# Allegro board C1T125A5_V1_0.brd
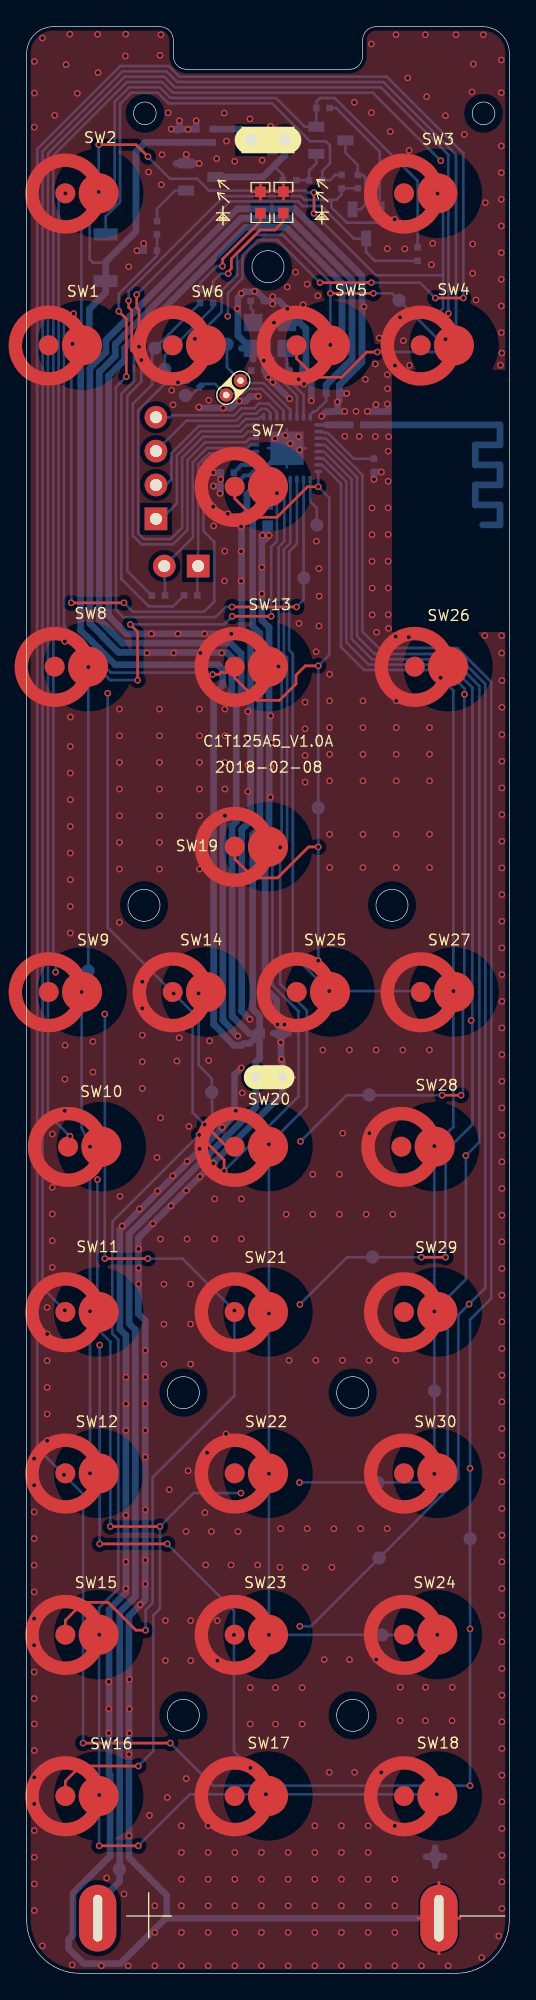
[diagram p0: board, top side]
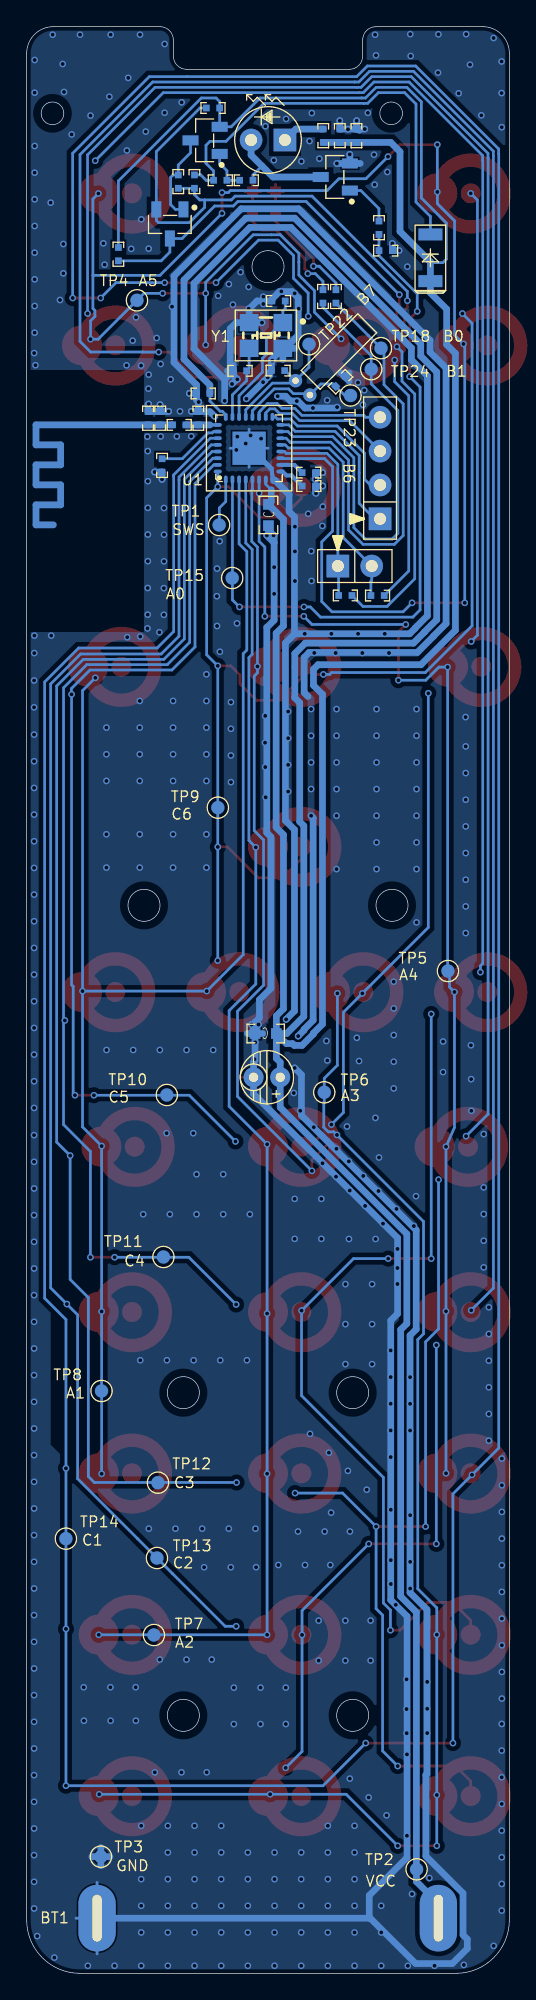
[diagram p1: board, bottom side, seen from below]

Outline 36.2 x 146 mm; copper layers: TOP, BOTTOM. Coordinates in mm from the lower left corner of the outline.
Outline path: circle c8.8,80.1 r1.2 ; circle c8.86,139.5 r0.85 ; circle c11.75,43.55 r1.2 ; circle c11.75,19.35 r1.2 ; circle c18.1,128 r1.2 ; circle c24.45,43.55 r1.2 ; circle c24.45,19.35 r1.2 ; circle c27.4,80.1 r1.2 ; circle c34.26,139.5 r0.85 ; 0,144 0,4 arc(1.17,1.17) 4,0 32.2,0 arc(35.03,1.17) 36.2,4 36.2,144 arc(35.61,145.41) 34.2,146 26.2,146 arc(25.49,145.71) 25.2,145 25.2,143.8 arc(24.91,143.09) 24.2,142.8 12,142.8 arc(11.29,143.09) 11,143.8 11,145 arc(10.71,145.71) 10,146 2,146 arc(0.59,145.41) 0,144

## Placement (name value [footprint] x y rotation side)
BT1  3V_2xAAA  [BAT_2DIP]  18.12 4.14 0 bottom
C1  2pF  [0402]  23.33 116.63 90 bottom
C2  2pF  [0402]  26.18 116.63 90 bottom
C3  1uF  [0603C]  18.07 109.38 90 bottom
C4  1uF  [0402]  26.04 113.1 270 bottom
C5  NC  [0402]  20.2 120.19 180 bottom
C6  NC  [0402]  17.31 125.43 180 bottom
C7  1uF  [0402]  15.04 111.55 0 bottom
C8  0.1uF  [0402]  22.96 118.49 180 bottom
C9  1uF  [0402]  15.04 112.56 180 bottom
C10  NC  [0402]  12.67 119.37 315 bottom
C11  NC  [0402]  17.35 120.21 180 bottom
C12  4.7uF  [0402]  11.47 137.82 90 bottom
C13  0.1uF  [0402]  12.71 137.82 90 bottom
C19  10uF  [0603C]  18.27 70.49 0 bottom
CD1  220uF/10V  [CD2P0_4P0B]  18.18 67.21 0 bottom
D1  LED  [LED_TH_2P54MM_2PIN]  18.1 137.5 180 bottom
D2  1N4148  [SOD80]  5.92 128.67 90 bottom
J1  HEADER 4  [HDR254F-1X4X850]  9.7 116.71 270 bottom
J2  HEADER 2  [HDR254F-1X2X850]  10.32 105.55 0 bottom
L1  2nH  [0402]  27.1 116.63 90 bottom
LED1  LED  [0603-LED]  19.26 132.82 90 top
LED2  LED  [0603-LED]  17.53 132.81 90 top
Q1  A1015  [SOT-23]  22.82 137.47 90 bottom
Q2  C1815  [SOT-23]  13.05 134.72 90 bottom
Q3  C1815  [SOT-23]  25.46 131.2 0 bottom
R1  2.4nH  [0402]  24.76 116.13 0 bottom
R2  1K  [0402]  13.98 125.77 90 bottom
R3  1K  [0402]  13 125.77 90 bottom
R5  1  [0402]  13.96 137.82 270 bottom
R6  NC  [0402]  9.27 129.21 0 bottom
R7  10K  [0402]  29.32 128.94 90 bottom
R8  100  [0402]  9.78 130.92 90 bottom
R9  10K  [0402]  19.73 134.48 0 bottom
R10  22K  [0402]  21.68 134.48 0 bottom
R11  10K  [0402]  24.83 134.38 90 bottom
R12  47K  [0402]  23.62 134.38 270 bottom
R13  NC  [0402]  22.23 139.9 0 bottom
R14  000/NC  [0402]  12.3 103.34 0 bottom
R15  000/NC  [0402]  9.88 103.33 0 bottom
SW1  SW2PIN  [SW_OUT6_IN3]  4.15 122.1 0 top
SW2  SW2PIN  [SW_OUT6_IN3]  5.4 133.5 0 top
SW3  SW2PIN  [SW_OUT6_IN3]  30.8 133.5 0 top
SW4  SW2PIN  [SW_OUT6_IN3]  32.05 122.1 0 top
SW5  SW2PIN  [SW_OUT6_IN3]  22.75 122.1 0 top
SW6  SW2PIN  [SW_OUT6_IN3]  13.45 122.1 0 top
SW7  SW2PIN  [SW_OUT6_IN3]  18.1 111.5 0 top
SW8  SW2PIN  [SW_OUT6_IN3]  4.6 98 0 top
SW9  SW2PIN  [SW_OUT6_IN3]  4.15 73.6 0 top
SW10  SW2PIN  [SW_OUT6_IN3]  5.6 62 0 top
SW11  SW2PIN  [SW_OUT6_IN3]  5.4 49.6 0 top
SW12  SW2PIN  [SW_OUT6_IN3]  5.4 37.5 0 top
SW13  SW2PIN  [SW_OUT6_IN3]  18.1 98 0 top
SW14  SW2PIN  [SW_OUT6_IN3]  13.45 73.6 0 top
SW15  SW2PIN  [SW_OUT6_IN3]  5.4 25.4 0 top
SW16  SW2PIN  [SW_OUT6_IN3]  5.4 13.3 0 top
SW17  SW2PIN  [SW_OUT6_IN3]  18.1 13.3 0 top
SW18  SW2PIN  [SW_OUT6_IN3]  30.8 13.3 0 top
SW19  SW2PIN  [SW_OUT6_IN3]  18.1 84.5 0 top
SW20  SW2PIN  [SW_OUT6_IN3]  18.1 62 0 top
SW21  SW2PIN  [SW_OUT6_IN3]  18.1 49.6 0 top
SW22  SW2PIN  [SW_OUT6_IN3]  18.1 37.5 0 top
SW23  SW2PIN  [SW_OUT6_IN3]  18.1 25.4 0 top
SW24  SW2PIN  [SW_OUT6_IN3]  30.8 25.4 0 top
SW25  SW2PIN  [SW_OUT6_IN3]  22.75 73.6 0 top
SW26  SW2PIN  [SW_OUT6_IN3]  31.6 98 0 top
SW27  SW2PIN  [SW_OUT6_IN3]  32.05 73.6 0 top
SW28  SW2PIN  [SW_OUT6_IN3]  30.6 62 0 top
SW29  SW2PIN  [SW_OUT6_IN3]  30.8 49.6 0 top
SW30  SW2PIN  [SW_OUT6_IN3]  30.8 37.5 0 top
TP1  SWS  [TP100]  21.77 108.63 180 bottom
TP2  VDD  [TP100]  6.95 7.8 180 bottom
TP3  GND  [TP100]  30.63 8.75 180 bottom
TP4  A5  [TP100]  27.93 125.48 180 bottom
TP5  A4  [TP100]  4.6 75.18 180 bottom
TP6  A3  [TP100]  13.88 66.08 180 bottom
TP7  A2  [TP100]  26.66 25.38 180 bottom
TP8  A1  [TP100]  30.59 43.68 180 bottom
TP9  C6  [TP100]  21.86 87.43 180 bottom
TP10  C5  [TP100]  25.69 65.88 180 bottom
TP11  C4  [TP100]  25.94 53.73 180 bottom
TP12  C3  [TP100]  26.35 36.8 180 bottom
TP13  C2  [TP100]  26.43 31.15 180 bottom
TP14  C1  [TP100]  33.26 32.6 180 bottom
TP15  A0  [TP100]  20.78 104.65 180 bottom
TP18  B0  [TP100]  9.63 121.89 180 bottom
TP22  B7  [TP100]  15.02 122.18 180 bottom
TP23  B6  [TP100]  11.91 118.34 180 bottom
TP24  B1  [TP100]  10.36 120.31 180 bottom
U1  TLSR8232F512ET32  [QFN_5X5_32PIN_0P5_2P50X2P50]  19.52 114.38 90 bottom
Y1  24Mhz  [OSCCC250X320X110]  18.25 122.84 270 bottom
Y2  NC/32.768KHz - 9pf - +/-20ppm  [OSC_2X6]  12.67 121.74 315 bottom

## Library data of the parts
BT1 = BATTERY_2xAAA_3V
C1 C2 C5 C6 C10 C11 = C1608_NC
C3 C4 C7-C9 = C1608X5R1C105M
C12 = C1608X5R1A226M
C13 = C1005X5R1C104K
C19 = C1608X5R0J106M
CD1 = CD_220uF_16V
D1 = Led_Th_3mm_1: User Part Number: partnum; Tolerance: RichardLC
D2 = Diode_1N4148
J1 = HEADER 4: User Part Number: pn; Tolerance: RichardLC
J2 = HEADER 2: User Part Number: pn; Tolerance: RichardLC
L1 = MLK1608_000R
LED1 LED2 = 0603D_Green
Q1 = PNP_A1015
Q2 Q3 = NPN_C1815
R1 = RS0603K000JT
R2 R3 = RS0603K102JT
R5 = RS0805K1R0JT
R6 R13-R15 = RS0402_NC
R7 R9 R11 = RS0402K103JT
R8 = RS0402K101JT
R10 = RS0402K223JT
R12 = RS0402K473JT
SW1-SW30 = SW2PIN_0
TP1-TP15 TP18 TP22-TP24 = TestPad100
U1 = TLSR8232F512ET32
Y1 = CRYSTAL4/SM_0: Tolerance: RichardLC
Y2 = OSC_2x6_2pin_16Mhz

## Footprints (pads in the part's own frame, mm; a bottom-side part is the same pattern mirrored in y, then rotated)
0402
  rect 0.5x0.5 smd: 1(-0.5,0) 2(0.5,0)
0603-LED
  rect 0.8x0.8 smd: A(-0.8,0) C(0.8,0)
0603C
  rect 0.8x0.8 smd: 1(-0.8,0) 2(0.8,0)
BAT_2DIP
  oval 2.8x5 hole 0.7x3.5: 1(-12.8,0) 2(12.8,0)
CD2P0_4P0B
  round 1.5 hole 0.7: 1(-1,0) 2(1,0)
HDR254F-1X2X850
  rect 1.7x1.7 hole 0.9: 1(2.54,0)
  round 1.7 hole 0.9: 2(0,0)
HDR254F-1X4X850
  rect 1.7x1.7 hole 0.9: 1(7.62,0)
  round 1.7 hole 0.9: 2(5.08,0) 3(2.54,0) 4(0,0)
LED_TH_2P54MM_2PIN
  rect 1.7x1.7 hole 0.9: A(1.27,0)
  round 1.7 hole 0.9: C(-1.27,0)
OSC_2X6
  round 1 hole 0.5: 1(4,0.76) 2(4,-0.76)
OSCCC250X320X110
  rect 1.3x1.4 smd: 1(-0.965,1.265) 2(-0.965,-1.265) 3(0.965,-1.265) 4(0.965,1.265)
QFN_5X5_32PIN_0P5_2P50X2P50
  oval 0.6x0.28 smd: 1(-2.35,1.75) 2(-2.35,1.25) 3(-2.35,0.75) 4(-2.35,0.25) 5(-2.35,-0.25) 6(-2.35,-0.75) 7(-2.35,-1.25) 8(-2.35,-1.75) 17(2.35,-1.75) 18(2.35,-1.25) 19(2.35,-0.75) 20(2.35,-0.25) 21(2.35,0.25) 22(2.35,0.75) 23(2.35,1.25) 24(2.35,1.75)
  oval 0.28x0.6 smd: 9(-1.75,-2.35) 10(-1.25,-2.35) 11(-0.75,-2.35) 12(-0.25,-2.35) 13(0.25,-2.35) 14(0.75,-2.35) 15(1.25,-2.35) 16(1.75,-2.35) 25(1.75,2.35) 26(1.25,2.35) 27(0.75,2.35) 28(0.25,2.35) 29(-0.25,2.35) 30(-0.75,2.35) 31(-1.25,2.35) 32(-1.75,2.35)
  rect 2.5x2.5 smd: 33(0,0)
SOD80
  rect 0.9x1.8 smd: A(-1.75,0) C(1.75,0)
SOT-23
  rect 0.75x1.2 smd: 1(-1.016,-1.092) 2(1.016,-1.092) 3(0,1.092)
SW_OUT6_IN3
  round 3 smd: 1(0,0)
  custom 1.5x1.5 smd: 2(-2.5,0)
TP100
  round 1 smd: 1(0,0)

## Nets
GND: BT1.2(-) C1.2 C2.2 C3.1 C4.2 C5.1 C6.1 C7.1 C8.1 C9.2 C10.1 C11.1 C12.2 C13.2 C19.2 CD1.2 L1.2 LED1.C(CATHODE) LED2.C(CATHODE) Q2.2(E) R6.1 TP3.1(TP) U1.8(DVSS) U1.33(GND) Y1.2 Y1.4
TL_32INPUT: C10.2 TP23.1(TP) U1.20(P0N/I2C_MCK/URTS/B[6]) Y2.1
TL_32OUTPUT: C11.2 TP22.1(TP) U1.21(P1/I2C_MSD/UCTS/B[7]) Y2.2
TL_ANT: C1.1 R1.1 U1.25(ANT)
TL_AVDD3: BT1.1(+) C3.2 C8.2 C12.1 C13.1 C19.1 CD1.1 D2.A Q1.2(E) R5.2 R7.2 R13.1 TP2.1(TP) U1.7(DVDD3) U1.24(AVDD3)
TL_B2: J1.1 U1.16(P2/MDI/UCTS/I2CMCK/B[2])
TL_B3: J1.2 U1.17(P0/MCK/URTS/I2CMSD/B[3])
TL_COL0: SW1.1 SW2.1 SW3.1 SW4.1 SW5.1 SW6.1 TP4.1(TP) U1.11(P5/I2C_CK_MCK/A[5])
TL_COL1: SW7.1 SW8.1 SW9.1 SW10.1 SW11.1 SW12.1 TP5.1(TP) U1.6(P2/URX/I2C_MSD/CK/A[4])
TL_COL2: SW13.1 SW14.1 SW15.1 SW16.1 SW17.1 SW18.1 TP6.1(TP) U1.5(P4/UTX/I2C_MCK/DI/A[3])
TL_COL3: SW19.1 SW20.1 SW21.1 SW22.1 SW23.1 SW24.1 TP7.1(TP) U1.4(P1N/URTS/A[2])
TL_COL4: SW25.1 SW26.1 SW27.1 SW28.1 SW29.1 SW30.1 TP8.1(TP) U1.3(P3N/UCTS/A[1])
TL_DVDD3F: C9.1 U1.10(DVDD3_F)
TL_IRCONTROL: J2.2 R15.2 U1.13(P5/A[7])
TL_IRIN: J2.1 R14.2 U1.12(P4N/I2C_SD_MSD/A[6])
TL_IROUT: R6.2 R8.1 TP15.1(TP) U1.2(P0/P3/A[0])
TL_LED1: R3.1 TP18.1(TP) U1.14(P3/MCN/B[0])
TL_LED2: R2.1 TP24.1(TP) U1.15(P1/MDO/B[1])
TL_ROW0: SW1.2 SW7.2 SW13.2 SW19.2 SW25.2 TP9.1(TP) U1.32(P4/C[6])
TL_ROW1: SW2.2 SW8.2 SW14.2 SW20.2 SW26.2 TP10.1(TP) U1.31(CK/I2C_MCK/MCK/URX/C[5])
TL_ROW2: SW3.2 SW9.2 SW15.2 SW21.2 SW27.2 TP11.1(TP) U1.30(DI/I2C_MSD/MDI/UTX/C[4])
TL_ROW3: SW4.2 SW10.2 SW16.2 SW22.2 SW28.2 TP12.1(TP) U1.29(DO/P5N/MDO/URTS/C[3])
TL_ROW4: SW5.2 SW11.2 SW17.2 SW23.2 SW29.2 TP13.1(TP) U1.28(CN/P0N/MCN/UCTS/C[2])
TL_ROW5: SW6.2 SW12.2 SW18.2 SW24.2 SW30.2 TP14.1(TP) U1.27(P2N/C[1])
TL_RST: C4.1 U1.26(RESETB)
TL_SWS: TP1.1(TP) U1.1(SWS/P3/C[7])
TL_URX: J1.4 U1.19(P4/URX/B[5])
TL_UTX: J1.3 U1.18(P1N/UTX/B[4])
TL_VDDDEC: C7.2 U1.9(VDDDEC)
TL_XC1: C5.2 U1.23(XC1) Y1.3
TL_XC2: C6.2 U1.22(XC2) Y1.1
N14595282: C2.1 L1.1 R1.2
N14596477: LED2.A(ANODE) R3.2
N14596527: LED1.A(ANODE) R2.2
N14600673: Q3.2(E) R11.1 R12.2 R13.2 R15.1
N14600711: D1.A(ANODE) R5.1
N14600791: D2.C R10.2 R12.1
N14601003: Q2.1(B) R8.2
N14601035: D1.C(CATHODE) Q2.3(C) R9.1
N14601075: Q1.3(C) Q3.1(B) R11.2
N14601095: Q1.1(B) R9.2 R10.1
N14601159: Q3.3(C) R7.1 R14.1

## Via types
v1: diameter 0.5, hole 0.3, TOP to BOTTOM, 638 vias

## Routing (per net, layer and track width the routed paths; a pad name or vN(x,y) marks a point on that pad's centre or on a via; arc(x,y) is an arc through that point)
GND: length 494.7
  TOP w0.2: CD1.2 19.18,68.13 ; CD1.2 20.11,67.21 ; CD1.2 19.18,66.28 ; BT1.2 32.5,4.14 ; BT1.2 30.92,6.82 ; BT1.2 30.92,1.46 ; BT1.2 29.34,4.14 ; 17.53,133.03 LED2.C ; LED2.C 17.53,134.19 ; LED2.C 16.96,133.61 ; LED2.C 18.11,133.61 ; 19.26,133.04 LED1.C ; LED1.C 18.68,133.62 ; LED1.C 19.83,133.62 ; LED1.C 19.26,134.2
  BOTTOM w0.2: 19.52,112.96 U1.33 ; U1.33 17.77,112.63 17.77,112.4 ; U1.33 20.95,114.38 ; U1.33 18.09,114.38 ; U1.33 19.52,115.81 ; 30.92,1.46 BT1.2 ; BT1.2 32.5,4.14 ; BT1.2 30.92,6.82
  BOTTOM w0.28: U1.8 17.77,112.4 17.81,112.44 17.81,112.87 19.57,114.63
  BOTTOM w0.5: C10.1 12.01,119.42 ; C10.1 12.62,120.03 ; C10.1 12.01,120.03 ; 11.24,138.22 C12.2 ; C12.2 v1(10.84,138.32) ; C12.2 11.47,138.88 11.45,138.9 v1(11.45,138.95) ; C12.2 C13.2 v1(12.71,138.95) ; v1(14.87,86.82) 14.71,86.66 14.71,71.48 15.39,70.8 15.39,70.74 v1(15.84,70.29) ; 19.07,70.9 v1(19.33,71.16) ; 19.07,70.9 19.07,71.33 18.74,71.66 18.74,73.02 17.88,73.88 17.88,85.24 18.19,85.54 18.19,100.94 17.64,101.49 17.64,107.3 ; 19.07,70.9 19.07,70.9 ; v1(26.6,112.6) 26.6,112.6 C4.2 26.04,112.06 v1(26.05,112.05) ; 21.35,119.54 23.65,121.84 23.65,126.75 19.46,130.94 16.38,130.94 7.34,121.9 7.34,121.01 6.14,119.81 6.14,101.82 7.07,100.89 7.07,100.87 7.48,100.46 16.11,100.46 16.11,100.46 ; 21.35,119.54 v1(21.35,117.94) ; 21.35,119.54 C5.1 ; C8.1 23.99,118.49 v1(24,118.5) ; C8.1 23.46,119.13 25.15,120.82 25.15,127.3 20.11,132.34 15.8,132.34 7.09,123.62 5.94,122.48 5.94,121.59 4.74,120.39 4.74,101.24 5.67,100.31 5.67,100.29 6.9,99.06 15.01,99.06 15.39,98.69 15.39,96.05 15.1,95.77 ; C8.1 23.46,118.01 v1(23.3,117.85) 23.33,117.82 C1.2 ; 17.64,107.3 17.64,107.81 v1(17.68,107.85) 18.07,108.24 ; 17.64,107.3 v1(18.19,107.84) 18.07,107.96 18.07,108.24 ; TP3.1 29.95,8.75 ; TP3.1 30.63,8.07 ; TP3.1 31.31,8.75 ; TP3.1 30.63,9.43 ; v1(26.2,117.65) 26.18,117.63 C2.2 ; Y1.2 20.49,123.8 20.93,123.36 20.93,120.43 C5.1 ; Y1.2 19.52,124.83 18.92,125.43 C6.1 17.81,125.56 17.24,126.13 16.3,126.13 15.84,125.66 15.84,122.85 16.82,121.87 ; Y1.2 18.55,123.8 v1(18.55,123.8) ; v1(20.8,119.2) 20.45,119.55 v1(20.4,119.55) 20.7,119.85 C5.1 ; v1(8.27,129.21) R6.1 v1(8.77,129.74) ; C5.1 20.7,120.62 ; C5.1 21.13,120.19 ; 16.11,100.46 16.79,99.78 16.79,86.45 16.11,85.78 16.11,72.18 v1(16.74,71.55) ; 16.11,100.46 16.11,109.23 16.52,109.63 16.52,110.92 17.56,111.97 17.61,111.97 17.68,112.03 ; C19.2 18.5,70.49 ; C19.2 19.07,70.9 ; C19.2 19.65,70.49 ; C19.2 19.07,69.83 ; v1(14,111.55) 14,111.55 C7.1 14.54,111.04 v1(14.5,111) ; Q2.2 11.96,136.41 v1(11.97,136.42) ; Q2.2 v1(12.94,135.74) ; Q2.2 11.18,135.74 ; 16.82,121.87 16.11,121.87 ; 16.82,121.87 Y1.4 ; 10.51,4.14 10.51,5.84 7.67,8.68 7.67,26.78 8.89,28 8.89,48.96 8.39,49.47 8.39,55.16 19.18,65.96 CD1.2 19.18,68.33 19.07,68.44 19.07,69.83 ; 10.51,4.14 10.43,4.14 7.02,0.73 4.27,0.73 3.15,1.85 3.15,2.56 3.47,2.88 3.47,6 6.26,8.79 6.26,14.88 6.18,14.96 6.18,27.29 7.45,28.56 7.45,47.84 6.99,48.3 6.99,55.74 15.59,64.34 15.59,67.39 v1(16.1,67.9) ; 10.51,4.14 BT1.2 ; v1(14.55,112.05) 14.54,112.06 C9.2 14.01,112.56 v1(14,112.55) ; 19.07,70.9 v1(18.81,71.16) ; 22.46,117.13 v1(22.11,116.78) ; 18.07,108.24 C3.1 ; v1(23.85,117.15) 23.83,117.13 C1.2 ; 12.88,117.4 v1(14.73,117.4) 15.33,117.4 15.86,117.92 16.42,117.92 16.78,118.28 v1(17.38,118.28) ; Y1.4 16.99,121.05 ; Y1.4 17.85,121.01 C11.1 17.97,120.09 17.97,119.86 18.36,119.46 18.36,119.45 v1(19.72,118.09) ; v1(27.05,117.7) 27.1,117.65 L1.2 C2.2 ; v1(25.55,117.15) 25.57,117.13 C2.2 ; 19.07,69.83 v1(19.06,69.82) ; C1.2 22.78,117.13 22.75,117.1
  vias: v1(0.58,143.39) v1(0.58,141.02) v1(0.57,138.46) v1(0.56,38.6) v1(0.56,36.6) v1(0.56,34.6) v1(0.56,32.6) v1(0.56,30.61) v1(0.56,28.61) v1(0.56,26.61) v1(0.56,24.61) v1(0.56,22.61) v1(0.56,20.61) v1(0.57,18.7) v1(0.57,16.7) v1(0.57,14.71) v1(0.57,12.71) v1(0.57,10.71) v1(0.57,8.71) v1(0.57,6.71) v1(0.57,4.71) v1(1.18,145.15) v1(1.18,2.06) v1(1.53,49.95) v1(1.53,47.95) v1(1.53,45.95) v1(1.53,43.95) v1(1.53,41.95) v1(1.53,39.95) v1(1.92,62.95) v1(1.92,58.95) v1(1.92,56.95) v1(1.92,54.95) v1(1.92,52.95) v1(2.1,139.35) v1(2.88,69.61) v1(2.87,67.06) v1(2.85,64.69) v1(2.95,143.15) v1(3.24,145.44) v1(3.28,94.22) v1(3.27,92.02) v1(3.27,90.02) v1(3.27,88.02) v1(3.27,86.02) v1(3.27,84.02) v1(3.27,82.02) v1(3.27,80.02) v1(3.27,78.02) v1(3.41,0.63) v1(3.8,141) v1(4.97,69.89) v1(4.97,67.59) v1(5.32,145.43) v1(5.35,142.55) v1(5.61,0.56) v1(6,7.15) v1(6.16,21.86) v1(6.16,19.84) v1(6.16,18.02) v1(6.96,94.82) v1(6.96,92.82) v1(6.96,90.82) v1(6.96,88.82) v1(6.96,86.82) v1(6.96,84.82) v1(6.96,82.82) v1(6.96,78.82) v1(7,58.28) v1(7.16,56.05) v1(7.3,5.95) v1(7.43,145.44) v1(7.4,143.8) v1(7.45,44.72) v1(7.45,42.72) v1(7.45,40.72) v1(7.44,34.36) v1(7.44,30.86) v1(7.44,28.86) v1(7.61,0.56) v1(7.65,128) v1(7.71,22.05) v1(7.71,19.82) v1(7.7,18.01) v1(7.68,16.42) v1(7.68,10.32) v1(8.39,54.33) v1(8.39,52.9) v1(8.39,51.7) v1(8.46,57.33) v1(8.52,27.64) v1(8.67,74.37) v1(8.67,72.37) v1(8.67,70.37) v1(8.67,68.37) v1(8.67,66.37) v1(8.9,46.72) v1(8.9,44.72) v1(8.9,42.72) v1(8.9,40.72) v1(8.9,38.72) v1(8.89,34.77) v1(8.89,30.99) v1(8.89,29.2) v1(9.03,99.03) v1(9.15,135.1) v1(9.21,11.85) v1(9.35,100.47) v1(9.47,56.23) v1(9.61,5.07) v1(9.61,3.06) v1(9.61,0.56) v1(9.78,61.19) v1(9.81,58.67) v1(10,143.85) v1(9.96,94.82) v1(9.96,92.82) v1(9.96,90.82) v1(9.96,88.82) v1(9.96,86.82) v1(9.96,84.82) v1(9.96,82.82) v1(10.04,64.16) v1(10.03,55.08) v1(10.07,145.4) v1(10.1,134.15) v1(10.15,136.4) v1(10.29,51.69) v1(10.29,48.69) v1(10.29,45.69) v1(10.4,26.46) v1(10.4,23.46) v1(10.61,139.53) v1(10.55,13.19) v1(10.69,36.27) v1(10.82,57.55) v1(10.88,118.73) v1(10.98,117.64) v1(11.03,99.03) v1(10.96,59.8) v1(11.35,119.31) v1(11.35,100.47) v1(11.27,68.42) v1(11.44,70.17) v1(11.61,11.06) v1(11.61,9.06) v1(11.61,7.07) v1(11.61,5.07) v1(11.61,3.06) v1(11.61,0.56) v1(12.04,60.9) v1(11.97,58.71) v1(12.03,55.08) v1(11.95,33.14) v1(11.96,14.6) v1(12.1,138.3) v1(12.11,37.69) v1(12.18,63.52) v1(12.29,51.69) v1(12.29,48.69) v1(12.29,45.69) v1(12.3,26.45) v1(12.3,23.45) v1(12.92,117.47) v1(13.03,99.03) v1(12.96,94.82) v1(12.96,92.82) v1(12.96,90.82) v1(12.96,88.82) v1(12.96,86.82) v1(12.96,82.82) v1(12.96,61.84) v1(13,59.74) v1(13.35,100.47) v1(13.37,34.55) v1(13.43,30.63) v1(13.53,39.05) v1(13.61,11.06) v1(13.61,9.06) v1(13.61,7.07) v1(13.61,5.07) v1(13.61,3.06) v1(13.61,0.56) v1(13.66,117.98) v1(13.72,69.93) v1(13.65,68.47) v1(13.85,33.13) v1(13.99,110) v1(14.03,108.56) v1(14.01,60.76) v1(14.1,58.09) v1(14.1,55.09) v1(14.25,136.1) v1(14.3,26.45) v1(14.3,23.45) v1(14.63,99.03) v1(14.66,63.46) v1(14.81,139.52) v1(14.84,104.42) v1(14.86,106.67) v1(14.87,94.82) v1(14.87,92.82) v1(14.87,90.82) v1(14.87,88.82) v1(14.95,40.46) v1(14.98,137.42) v1(15.09,109.47) v1(15.35,100.47) v1(15.32,30.62) v1(15.6,135.9) v1(15.61,9.06) v1(15.61,7.07) v1(15.61,5.07) v1(15.61,3.06) v1(15.61,0.56) v1(15.69,64.69) v1(15.8,124.85) v1(15.85,33.13) v1(15.94,117.92) v1(16.1,126) v1(16.08,108.5) v1(16.08,106.64) v1(16.08,104.42) v1(16.1,58.09) v1(16.1,55.09) v1(16.16,66.03) v1(16.59,94.64) v1(16.59,92.64) v1(16.59,90.64) v1(16.59,88.64) v1(16.75,139.08) v1(16.76,21.43) v1(16.76,18.7) v1(17.1,126.15) v1(17.32,30.62) v1(17.64,105.46) v1(17.64,103.46) v1(17.61,9.06) v1(17.61,7.07) v1(17.61,5.07) v1(17.61,3.06) v1(17.61,0.56) v1(17.66,135.98) v1(17.78,120.95) v1(18.12,119.7) v1(18.3,138.53) v1(18.31,94.31) v1(18.32,92.3) v1(18.31,90.47) v1(18.28,88.2) v1(18.45,125.75) v1(18.45,125.2) v1(18.47,119.34) v1(18.62,115.1) v1(18.66,21.43) v1(18.66,18.7) v1(19.04,33.35) v1(18.99,30.46) v1(19.11,68.56) v1(19.4,115.34) v1(19.46,56.93) v1(19.55,126.48) v1(19.55,124.85) v1(19.61,9.06) v1(19.61,7.07) v1(19.61,5.07) v1(19.61,3.06) v1(19.61,0.56) v1(19.68,45.98) v1(19.77,114.73) v1(20.16,127.59) v1(20.4,115.26) v1(20.43,101.25) v1(20.47,114.25) v1(20.73,125.15) v1(20.66,21.43) v1(20.66,18.7) v1(20.88,95.34) v1(20.88,93.34) v1(20.88,91.34) v1(20.88,89.34) v1(20.89,30.45) v1(21.04,126.69) v1(21.04,33.35) v1(21.46,59.93) v1(21.46,56.93) v1(21.61,11.06) v1(21.61,9.06) v1(21.61,7.07) v1(21.61,5.07) v1(21.61,3.06) v1(21.61,0.56) v1(21.73,107.41) v1(21.71,99.12) v1(21.68,45.98) v1(21.84,125.81) v1(21.92,105.36) v1(21.93,103.28) v1(21.92,101.05) v1(22.21,69.25) v1(22.32,23.53) v1(22.72,97.43) v1(22.72,95.43) v1(22.72,93.43) v1(22.72,91.43) v1(22.72,89.43) v1(22.72,85.43) v1(22.72,82.93) v1(22.69,15.08) v1(22.89,30.45) v1(23.04,33.35) v1(23.46,59.93) v1(23.46,56.93) v1(23.61,11.06) v1(23.61,9.06) v1(23.61,7.07) v1(23.61,5.07) v1(23.61,3.06) v1(23.61,0.56) v1(23.7,63.01) v1(23.68,45.98) v1(23.86,115.28) v1(24.21,69.25) v1(24.21,23.53) v1(24.57,140.32) v1(24.59,15.07) v1(24.7,117.15) v1(24.94,115.27) v1(25.04,33.35) v1(25.22,95.43) v1(25.22,93.43) v1(25.22,91.43) v1(25.22,89.43) v1(25.22,85.43) v1(25.22,82.93) v1(25.3,125) v1(25.4,119.55) v1(25.46,56.93) v1(25.61,11.06) v1(25.61,9.06) v1(25.61,7.07) v1(25.61,5.07) v1(25.61,3.06) v1(25.61,0.56) v1(25.7,63.01) v1(25.68,45.98) v1(25.85,144.7) v1(25.85,139.54) v1(25.9,109.9) v1(25.9,107.9) v1(25.9,105.9) v1(25.91,103.89) v1(25.91,101.89) v1(26.15,120.7) v1(26.15,115.27) v1(26.25,100.58) v1(26.21,69.25) v1(26.21,23.53) v1(26.45,122.65) v1(26.59,15.07) v1(27.04,33.35) v1(27.05,129.35) v1(27.05,119.9) v1(27.07,118.85) v1(27.15,115.25) v1(27.12,114.17) v1(27.11,111.91) v1(27.11,109.91) v1(27.11,107.91) v1(27.11,105.91) v1(27.12,103.9) v1(27.12,101.9) v1(27.14,100.87) v1(27.27,138.13) v1(27.46,56.93) v1(27.61,131.55) v1(27.62,120.58) v1(27.61,11.06) v1(27.61,7.07) v1(27.61,5.07) v1(27.61,3.06) v1(27.61,0.56) v1(27.7,145.4) v1(27.68,100.26) v1(27.72,95.43) v1(27.72,93.43) v1(27.72,91.43) v1(27.72,89.43) v1(27.72,85.43) v1(27.72,82.93) v1(27.68,45.98) v1(28,124.2) v1(28.02,21.46) v1(28.01,18.95) v1(28.25,122.45) v1(28.21,69.25) v1(28.36,129.34) v1(28.58,142.16) v1(28.68,136.72) v1(28.71,120.6) v1(28.66,100.21) v1(29.61,0.56) v1(29.9,145.4) v1(29.92,21.45) v1(29.91,18.95) v1(30,140.74) v1(30.22,93.43) v1(30.22,91.43) v1(30.22,89.43) v1(30.22,85.43) v1(30.22,82.93) v1(30.21,69.25) v1(30.45,129.75) v1(30.36,128.15) v1(31.41,139.33) v1(31.61,0.56) v1(31.92,21.45) v1(31.91,18.95) v1(32.2,145.4) v1(32.83,137.92) v1(33.4,141.1) v1(33.5,143.2) v1(33.45,129.7) v1(33.45,127.5) v1(33.7,125.5) v1(34.12,1.18) v1(34.25,145.4) v1(34.4,132.8) v1(34.36,100.33) v1(35.41,2.79) v1(35.54,120.61) v1(35.6,143.5) v1(35.6,141.05) v1(35.6,137.05) v1(35.6,135.05) v1(35.6,133.05) v1(35.6,131.05) v1(35.6,129.05) v1(35.6,127.05) v1(35.6,125.05) v1(35.6,123.05) v1(35.64,121.52) v1(35.62,100.33) v1(35.63,99.02) v1(35.65,96.97) v1(35.65,94.95) v1(35.65,92.91) v1(35.65,90.91) v1(35.65,88.91) v1(35.65,86.91) v1(35.65,84.91) v1(35.65,82.91) v1(35.65,80.91) v1(35.65,78.91) v1(35.65,76.91) v1(35.65,74.91) v1(35.65,72.91) v1(35.65,70.91) v1(35.65,68.91) v1(35.65,66.91) v1(35.65,64.91) v1(35.65,62.87) v1(35.65,60.87) v1(35.65,58.87) v1(35.65,56.87) v1(35.65,54.87) v1(35.65,52.87) v1(35.65,50.87) v1(35.65,48.87) v1(35.65,46.87) v1(35.65,44.87) v1(35.65,42.87) v1(35.65,40.87) v1(35.65,38.87) v1(35.65,36.87) v1(35.65,34.87) v1(35.65,32.87) v1(35.65,30.86) v1(35.65,28.86) v1(35.65,26.86) v1(35.65,24.86) v1(35.65,22.86) v1(35.65,20.86) v1(35.65,18.86) v1(35.65,16.86) v1(35.65,14.87) v1(35.65,12.87) v1(35.65,10.87) v1(35.65,8.87) v1(35.65,6.87) v1(35.65,4.87)
TL_32INPUT: length 9.4
  BOTTOM w0.2: TP23.1 12.34,118.34 C10.2 13.2,119.2 14.14,119.2 Y2.1 15.06,118.47 16.19,118.47 16.55,118.83 17.63,118.83 19.27,117.2 U1.20
TL_32OUTPUT: length 9.4
  BOTTOM w0.2: TP22.1 15.02,120.46 Y2.2 ; Y2.2 16.22,119.26 17.77,119.26 19.77,117.26 U1.21 ; Y2.2 16.79,120.21 C11.2
TL_ANT: length 2.4
  BOTTOM w0.25: 22.45,116.13 U1.25
  BOTTOM w0.5: 22.45,116.13 C1.1 R1.1
TL_AVDD3: length 347.8
  BOTTOM w0.2: 5.92,128.36 5.86,128.3 4.98,128.3 4.72,128.57 4.72,131.27 6.6,133.15 6.6,140.37 7.68,141.45 9.99,141.45 10.79,140.65 11.08,140.65 18.7,140.65 20.86,138.49 Q1.2 R13.1 21.73,140.38 22,140.65 23.1,140.65 29.32,134.43 R7.2 ; C8.2 22.46,117.93 21.69,117.15 21.53,117.15 21.27,116.89 U1.24 ; 17.85,111.27 18.27,111.68 U1.7
  BOTTOM w0.5: C19.1 16.7,70.49 15.41,71.77 15.41,86.07 15.72,86.37 15.72,95.29 16.09,95.66 16.09,98.98 15.3,99.76 7.19,99.76 6.37,100.58 6.37,100.6 5.44,101.53 5.44,120.1 6.64,121.3 6.64,122.19 7.38,122.92 16.09,131.64 19.76,131.64 24.4,127 24.4,121.06 22.46,119.12 C8.2 ; C19.1 16.71,69.72 16.26,69.72 16.13,69.59 15.55,69.59 14.69,70.45 14.69,70.51 14.01,71.19 14.01,95.92 14.69,96.6 14.69,97.8 14.35,98.14 6.63,98.14 4.04,100.73 4.04,121.49 4.7,122.15 4.7,124.82 5.92,126.04 D2.A 5.92,128.36 8.2,130.64 8.2,136.62 8.9,137.32 C12.1 C13.1 R5.2 ; C19.1 17.47,71.81 16.94,72.34 16.94,85.4 17.49,85.95 17.49,100.51 16.94,101.06 16.94,109.05 C3.2 17.85,110.39 17.85,111.27 ; C19.1 17.47,68.62 17.18,68.33 CD1.1 17.18,64.95 7.69,55.45 7.69,48.73 8.15,48.27 8.15,28.27 6.97,27.09 6.97,7.82 ; 6.97,7.82 6.97,6.89 5.32,5.24 BT1.1 ; 6.97,7.82 TP2.1
TL_B2: length 12.5
  BOTTOM w0.2: U1.16 16.54,116.13 16.06,115.65 13.08,115.65 11.26,113.84 11.26,112.51 11.26,110.25 10.1,109.09 9.7,109.09
TL_B3: length 11.3
  BOTTOM w0.2: U1.17 17.55,116.73 17.39,116.57 16.42,116.57 15.89,116.05 12.91,116.05 10.86,114 10.86,113.34 10.86,113.34 10.86,112.05 10.43,111.63 J1.2
TL_COL0: length 134.9
  TOP w0.2: v1(7.3,102.79) v1(3.34,102.79) ; v1(22.77,126) v1(26,126) ; v1(5.4,133.6) 5.4,133.57 SW2.1 ; v1(9.1,136.25) 8.2,137.15 v1(5.4,137.15) ; v1(21.55,133.55) v1(21.55,132)
  BOTTOM w0.2: 31.23,127.35 26.2,127.35 v1(21.55,132) ; 31.23,127.35 31.23,124.86 31.08,124.72 31.08,124.26 31.41,123.93 v1(31.41,122.56) 30.84,122.56 TP4.1 27.4,126 v1(26,126) ; 31.23,127.35 31.23,133.08 v1(30.82,133.49) ; v1(22.77,122.13) v1(22.77,126) 22.77,126.83 19.21,130.39 17.84,130.39 17.17,130.39 15.78,129 15.78,128.33 15.78,127.37 14.62,126.2 14.62,124.59 v1(12.61,122.58) ; v1(5.4,137.15) v1(5.4,133.6) 5.4,132.73 4.11,131.44 4.11,122.88 v1(3.44,122.21) 3.34,122.11 v1(3.34,102.79) ; v1(21.55,133.55) 21.07,133.55 20.92,133.71 13.67,133.71 12.78,134.6 10.75,134.6 v1(9.1,136.25) ; U1.11 16.94,113.63 16.9,113.6 13.85,113.6 13.26,113.01 13.26,108.17 14.07,107.36 14.07,102.89 13.3,102.11 7.97,102.11 v1(7.3,102.79)
TL_COL1: length 90.6
  TOP w0.2: v1(7.77,101.16) 8.32,100.62 v1(8.32,96.98) ; v1(18.34,101.78) v1(15.41,101.78)
  BOTTOM w0.2: v1(7.77,101.16) 14.8,101.16 v1(15.41,101.78) ; v1(4.75,37.5) v1(4.75,49.65) v1(4.75,62) 4.12,63.44 v1(4.12,73.6) 4.48,73.97 4.48,75.05 TP5.1 4.63,75.2 v1(4.63,97.97) 5.28,97.97 6.27,96.98 v1(8.32,96.98) ; v1(18.34,101.78) 18.34,106.98 18.77,107.41 18.77,110.7 v1(18.77,111.01) U1.6
TL_COL2: length 154.4
  TOP w0.2: v1(5.44,9.56) v1(8.37,9.56) ; v1(14.81,60.18) 14.81,61 v1(12.93,62.88)
  BOTTOM w0.2: v1(8.37,9.56) 12.24,13.43 v1(17.94,13.43) v1(30.76,13.43) ; U1.5 19.27,111.29 19.32,111.24 19.32,107.39 18.89,106.96 v1(18.89,98.02) 18.89,97.54 19.13,97.3 19.13,85.71 18.43,85.01 18.43,74.11 20.39,72.15 20.39,65.76 v1(14.81,60.18) ; v1(5.44,9.56) v1(5.44,13.37) v1(5.44,25.4) 5.44,27.41 6.87,28.84 6.87,47.53 6.44,47.96 6.44,56.39 v1(12.93,62.88) 13.16,63.11 13.57,63.11 13.92,63.45 13.92,65.31 13.88,65.35 TP6.1 13.88,67.12 12.9,68.1 v1(12.9,73.5)
TL_COL3: length 101.8
  BOTTOM w0.2: v1(30.8,25.39) 26.67,25.39 TP7.1 26.65,25.39 v1(18.17,25.39) v1(18.17,37.47) v1(18.17,49.49) v1(18.17,62.18) 21.01,65.03 21.01,72.2 19.01,74.2 v1(19.01,84.45) 19.53,84.97 19.53,98.68 19.29,98.92 19.29,106.8 19.77,107.28 U1.4
TL_COL4: length 109.9
  BOTTOM w0.2: U1.3 20.27,107.21 19.69,106.63 19.69,99.24 19.96,98.97 19.96,76.4 v1(22.69,73.67) v1(32.01,73.67) ; v1(32.01,73.67) 32.01,96.2 v1(31.05,97.16) ; v1(32.01,73.67) 32.01,63.48 v1(30.58,62.05) v1(30.58,49.64) 30.58,43.69 TP8.1 30.58,43.67 v1(30.58,37.46)
TL_DVDD3F: length 1.9
  BOTTOM w0.3: C9.1 16.12,113.13 U1.10
TL_IRCONTROL: length 16.2
  BOTTOM w0.2: U1.13 16.81,114.63 16.57,114.4 13.52,114.4 12.46,113.34 12.46,107.69 J2.2 10.32,104.47 10.38,104.41 R15.2
TL_IRIN: length 14.6
  BOTTOM w0.2: R14.2 12.8,104.17 12.8,105.49 J2.1 12.86,113.17 13.69,114 16.74,114 16.87,114.13 U1.12
TL_IROUT: length 53.8
  TOP w0.2: v1(15.4,102.48) v1(20.24,102.48) ; v1(6.91,124.65) 7.48,124.08 v1(7.48,119.76)
  BOTTOM w0.2: v1(20.24,102.48) 20.77,103.01 20.77,104.63 TP15.1 20.77,104.67 U1.2 ; R8.1 R6.2 9.77,128.83 6.91,125.97 v1(6.91,124.65) ; v1(15.4,102.48) 14.93,102.48 14.16,101.71 7.24,101.71 6.69,102.26 6.69,118.97 v1(7.48,119.76)
TL_LED1: length 35.4
  BOTTOM w0.2: R3.1 10.59,122.86 10.59,122.86 TP18.1 9.4,121.66 9.4,119.15 7.96,117.71 7.96,107.83 8.62,107.17 10.97,107.17 12.06,108.26 12.06,112.84 12.06,113.5 13.39,114.83 16.44,114.83 16.74,115.13 U1.14
TL_LED2: length 35
  BOTTOM w0.2: R2.1 13.98,124.94 10.36,121.32 TP24.1 10.36,119.21 8.36,117.21 8.36,108 8.79,107.57 10.81,107.57 11.66,108.43 11.66,112.68 11.66,113.67 13.24,115.25 16.22,115.25 16.61,115.63 U1.15
TL_ROW0: length 102.3
  TOP w0.2: v1(21.87,111.49) 21.06,111.49 18.77,109.2 17.01,109.2 15.61,110.61 15.61,111.49 SW7.2 ; v1(21.87,98.06) 20.89,98.06 20.2,97.37 20.2,96.71 18.97,95.48 17.28,95.48 15.6,97.16 SW13.2 15.16,97.56 14.56,97.56 14.42,97.42 v1(13.95,97.42) ; v1(21.87,84.48) 21.13,84.48 18.81,82.16 17.02,82.16 15.62,83.56 15.62,84.48 SW19.2
  BOTTOM w0.2: v1(13.95,97.42) 13.47,97.42 13.33,97.56 6.3,97.56 2.79,101.06 2.79,123.75 v1(3.52,124.48) ; v1(21.87,75.96) v1(21.87,84.48) 21.87,87.42 TP9.1 21.87,87.43 v1(21.87,98.06) 22.7,98.89 22.7,110.66 v1(21.87,111.49) U1.32
TL_ROW1: length 141.5
  TOP w0.2: v1(13.35,63.66) 15,62 SW20.2 ; v1(32.58,65.86) v1(31.16,65.86)
  BOTTOM w0.2: v1(20.54,62.39) 24,65.86 25.67,65.86 TP10.1 25.71,65.86 v1(31.16,65.86) ; v1(2.86,99.89) 2.39,100.35 2.39,132.99 v1(2.9,133.5) ; v1(6.08,96.01) 6.08,78.44 v1(11.02,73.49) 12.45,72.07 12.45,64.56 v1(13.35,63.66) ; U1.31 22.16,113.13 23.57,111.72 23.57,99.48 25.3,97.75 31.45,97.75 32.85,96.35 32.85,95.94 v1(32.83,95.92) 32.83,74.14 32.71,74.02 32.71,65.99 v1(32.58,65.86)
TL_ROW2: length 241.8
  TOP w0.2: SW15.2 2.9,26.47 4.25,27.82 6.11,27.82 8.2,25.73 v1(8.92,25.73) ; v1(31.42,53.71) v1(29.61,53.71) ; v1(9.09,53.6) v1(5.86,53.6)
  BOTTOM w0.2: v1(29.61,53.71) 25.96,53.71 TP11.1 25.92,53.71 24.03,53.71 v1(20.49,50.16) ; U1.30 22.23,113.63 23.97,111.89 23.97,99.83 25.65,98.15 31.7,98.15 33.43,96.42 33.43,71.57 v1(33.33,71.47) 33.43,71.37 33.43,63.66 31.42,61.64 v1(31.42,53.71) ; v1(5.86,71.95) v1(5.86,53.6) ; v1(8.92,25.73) 8.92,27.25 9.44,27.77 9.44,37.19 15.58,43.33 v1(15.58,49.7) 11.68,53.6 v1(9.09,53.6) ; v1(31.06,135.95) 25.95,141.05 11.25,141.05 10.95,141.05 10.15,141.85 7.52,141.85 2,136.33 2,135.98 1.99,135.98 1.99,75.74 2.17,75.56 v1(2.17,75.09)
TL_ROW3: length 282
  TOP w0.2: v1(8.37,15.55) 7.41,15.55 7.4,15.55 4.04,15.55 2.9,14.41 SW16.2 ; v1(9.99,33.51) 9.52,33.51 v1(6.28,33.51)
  BOTTOM w0.2: v1(3.25,62.79) 1.59,64.44 1.59,136.14 1.6,136.15 1.6,136.5 7.35,142.25 10.32,142.25 11.12,141.45 11.43,141.45 26.57,141.45 31.63,136.39 v1(31.63,124.49) ; v1(5.31,59.53) 5.31,48.33 6.28,47.36 v1(6.28,33.51) ; v1(20.46,36.81) 26.34,36.81 TP12.1 26.37,36.81 31.12,36.81 31.58,37.27 31.58,50.68 32.94,52.05 v1(32.94,61.33) 33.95,62.34 33.95,96.55 31.95,98.55 25.91,98.55 24.37,100.09 24.37,111.84 24.37,112.05 22.29,114.13 U1.29 ; v1(16.07,36.02) 12.5,36.02 v1(9.99,33.51) 9.99,27.35 9.5,26.86 9.5,16.68 v1(8.37,15.55)
TL_ROW4: length 295.6
  TOP w0.2: v1(26.3,121.59) 25.5,121.59 23.61,119.7 21.65,119.7 20.25,121.1 SW5.2 ; v1(10.54,32.21) v1(5.48,32.21)
  BOTTOM w0.2: U1.28 22.36,114.63 24.77,112.22 24.77,112 24.77,100.29 26.11,98.95 32.15,98.95 34.4,96.7 34.4,51.41 v1(33.19,50.2) 32.38,49.39 32.38,37.1 27.87,32.58 TP13.1 25.27,29.98 21.31,26.03 v1(20.49,26.03) ; v1(16.78,15.41) 15.55,16.64 v1(15.55,25.38) 15.55,27.2 v1(10.54,32.21) ; v1(5.48,47.12) v1(5.48,32.21) ; v1(2.86,49.73) 1.19,51.39 1.19,136.31 1.2,136.32 1.2,136.66 7.19,142.65 10.48,142.65 11.28,141.85 11.6,141.85 26.75,141.85 32.2,136.4 32.2,122.4 31.4,121.6 27.5,121.6 27.5,121.59 v1(26.3,121.59)
TL_ROW5: length 334.2
  TOP w0.2: v1(10.77,17.27) v1(4.23,17.27) ; v1(25.85,126.8) v1(22,126.8) ; v1(32.75,125.65) v1(30.65,125.65)
  BOTTOM w0.2: v1(22,126.8) 18.81,129.99 17.34,129.99 16.18,128.83 16.18,127.12 15.09,126.03 15.09,124.29 v1(15.08,124.28) ; v1(10.77,17.27) 13.97,14.07 v1(33.25,14.07) v1(33.25,25.83) 33.25,32.59 TP14.1 33.25,32.6 v1(33.25,37.88) 33.25,49.03 34.85,50.63 34.85,96.85 32.3,99.4 26.41,99.4 25.17,100.64 25.17,112.27 25.17,112.38 22.42,115.13 U1.27 ; v1(4.23,17.27) 4.23,35.96 v1(2.8,37.39) 0.79,39.39 0.79,136.47 0.8,136.48 0.8,136.83 7.02,143.05 10.65,143.05 11.45,142.25 24.15,142.25 24.15,142.25 27,142.25 32.75,136.5 v1(32.75,125.65) ; v1(25.85,126.8) 29.5,126.8 v1(30.65,125.65)
TL_RST: length 5
  BOTTOM w0.2: C4.1 24.53,113.6 22.59,115.53 22.28,115.53 22.18,115.63 U1.26
TL_SWS: length 3.6
  BOTTOM w0.2: TP1.1 21.75,108.64 21.75,109.9 21.27,110.38 U1.1
TL_URX: length 10.1
  BOTTOM w0.2: J1.4 10.77,116.71 10.92,116.85 15.56,116.85 16.08,117.37 17.06,117.37 17.42,117.73 18.13,117.73 18.67,117.2 18.67,117.18 18.77,117.08 U1.19
TL_UTX: length 10.3
  BOTTOM w0.2: U1.18 18.27,117.03 17.97,117.33 17.59,117.33 17.23,116.97 16.25,116.97 15.73,116.45 11.98,116.45 9.7,114.17
TL_VDDDEC: length 2.1
  BOTTOM w0.3: U1.9 17.01,112.63 16.71,112.34 16.33,112.34 C7.2
TL_XC1: length 5.7
  BOTTOM w0.2: Y1.3 19.52,120.37 C5.2 19.7,119.46 20.77,118.39 U1.23
TL_XC2: length 10.2
  BOTTOM w0.2: C6.2 16.81,124.86 16.99,124.68 Y1.1 17.04,123.8 18.23,122.62 18.23,121.41 18.52,121.12 18.52,120.08 18.91,119.69 18.91,119.68 20.27,118.32 20.27,117.86 20.27,117.86 U1.22
N14595282: length 26.4
  BOTTOM w0.5: R1.2 C2.1 L1.1 35.5,116.13 35.5,114.63 33.65,114.63 33.65,113.13 35.5,113.13 35.5,111.63 33.65,111.63 33.65,110.13 35.5,110.13 35.5,108.63 34.2,108.63
N14596477: length 7.9
  TOP w0.2: LED2.A 17.53,131.4 14.69,128.56 v1(14.69,128.04)
  BOTTOM w0.2: R3.2 13,126.78 14.26,128.04 v1(14.69,128.04)
N14596527: length 8.9
  TOP w0.2: LED1.A 19.26,131.39 18.61,130.75 17.5,130.75 15.35,128.6 15.35,127.85 15.11,127.61 v1(15.11,127.48)
  BOTTOM w0.2: v1(15.11,127.48) 14.55,127.48 13.98,126.9 R2.2
N14600673: length 60.3
  TOP w0.2: v1(7.65,125.45) 7.65,124.95 7.88,124.72 7.88,121.72 v1(8.6,121)
  BOTTOM w0.2: R13.2 23.2,139.9 26.47,136.63 Q3.2 26.47,131.47 26.3,131.3 24,131.3 22.85,132.45 22.85,133 ; 22.85,133 23.22,133 23.62,133.4 R12.2 R11.1 ; 22.85,133 20.85,133 20.56,133.29 14.8,133.29 7.65,126.14 v1(7.65,125.45) ; R15.1 7.54,105.17 7.54,118.32 8.6,119.38 v1(8.6,121)
N14600711: length 3.2
  BOTTOM w0.5: R5.1 16.01,138.32 D1.A
N14600791: length 32.4
  BOTTOM w0.2: D2.C 5.92,131.77 7,132.85 7,140.2 7.85,141.05 9.82,141.05 10.62,140.25 10.92,140.25 18.4,140.25 21.25,137.4 22.45,137.4 22.75,137.1 22.75,135.75 22.18,135.18 R10.2 22.74,134.48 23.14,134.88 R12.1
N14601003: length 3.8
  BOTTOM w0.2: Q2.1 11.13,133.71 9.78,132.35 9.78,131.37 R8.2
N14601035: length 8.4
  BOTTOM w0.2: R9.1 19.23,134.87 18.55,135.55
  BOTTOM w0.5: D1.C 19.37,136.37 17.72,134.72 Q2.3
N14601075: length 6.8
  BOTTOM w0.2: Q1.3 23.91,136.54 24.83,135.62 R11.2 25.22,134.88 25.4,134.7 25.4,132.65 25.04,132.3 Q3.1
N14601095: length 3.2
  BOTTOM w0.2: R9.2 R10.1 21.18,135.2 21.73,135.74 Q1.1
N14601159: length 54.3
  TOP w0.2: v1(8.25,125.9) 8.25,124.92 8.43,124.74 v1(8.43,122)
  BOTTOM w0.2: v1(8.43,122) 8.05,121.62 8.05,119.41 7.09,118.45 7.09,104.59 9.17,102.51 10.97,102.51 R14.1 ; v1(8.25,125.9) 15.24,132.89 20.36,132.89 20.7,132.55 22.1,132.55 24.54,130.11 Q3.3 25.46,129.09 26.11,128.44 R7.1

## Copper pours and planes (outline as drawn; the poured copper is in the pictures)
GND on TOP: 4,0.3 1.38,1.38 0.3,4 0.3,144 0.8,145.2 2,145.7 10,145.7 10.49,145.49 10.7,145 10.7,143.8 11.08,142.88 12,142.5 24.2,142.5 25.12,142.88 25.5,143.8 25.5,145 25.71,145.49 26.2,145.7 34.2,145.7 35.4,145.2 35.9,144 35.9,120.25 27.4,120.25 27.4,100.6 35.9,100.6 35.9,4 34.82,1.38 32.2,0.3
GND on BOTTOM: 4,0.3 1.38,1.38 0.3,4 0.3,144 0.8,145.2 2,145.7 10,145.7 10.49,145.49 10.7,145 10.7,143.8 11.08,142.88 12,142.5 24.2,142.5 25.12,142.88 25.5,143.8 25.5,145 25.71,145.49 26.2,145.7 34.2,145.7 34.7,145.62 35.16,145.4 35.7,144.79 35.9,144 35.9,120.25 27.4,120.25 27.4,100.6 35.9,100.6 35.9,4 34.82,1.38 32.2,0.3 ; 24 cut-outs

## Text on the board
Ref Des/Silkscreen Bottom: B1 | B0 | A4 | VCC | A3 | A2 | C3 | C2 | SWS | C6 | A0 | A5 | C4 | GND | C5 | C1 | A1 | B6 | B7
User.Comments: AMJ-151029
Ref Des/Silkscreen Top: C1T125A5_V1.0A | 2018-02-08
COMPVAL_TYPE_BOTTOM: FIGURE | SIZE | 0.3 | 0.5 | 0.7 | 0.9 | 3.5x0.7 | DRILL CHART: TOP to BOTTOM | ALL UNITS ARE IN MILLIMETERS | PLATED | QTY | 638 | 2 | 8
